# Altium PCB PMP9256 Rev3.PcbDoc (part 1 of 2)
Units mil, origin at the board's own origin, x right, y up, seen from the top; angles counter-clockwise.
Board outline 5025 x 2070 mil, 4 copper layers (Top Layer, MidLayer1, MidLayer2, Bottom Layer), stack 90 mil thick; 116 components, 45 nets, 245 pads, 340 vias.
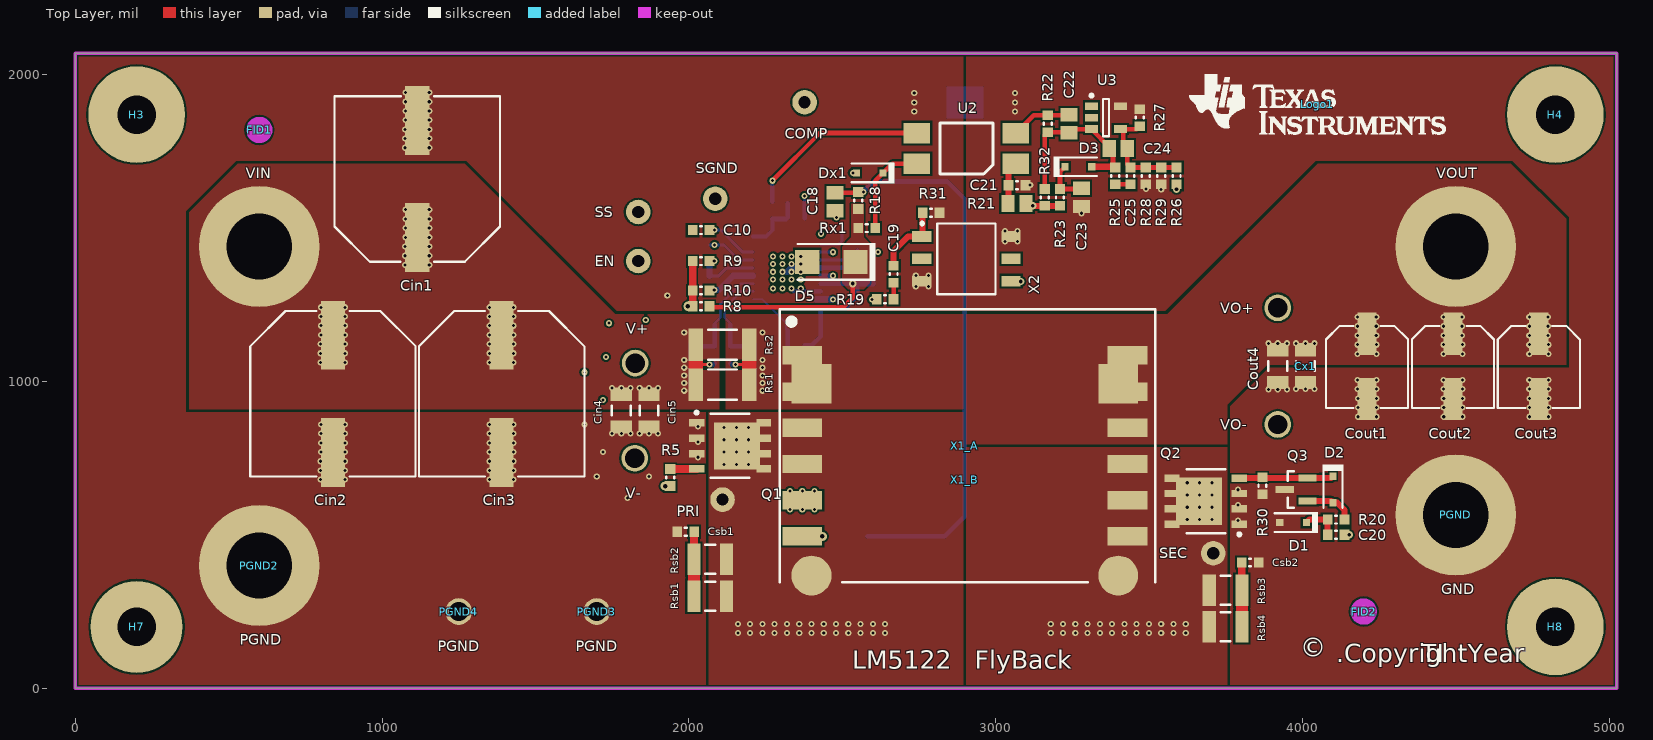
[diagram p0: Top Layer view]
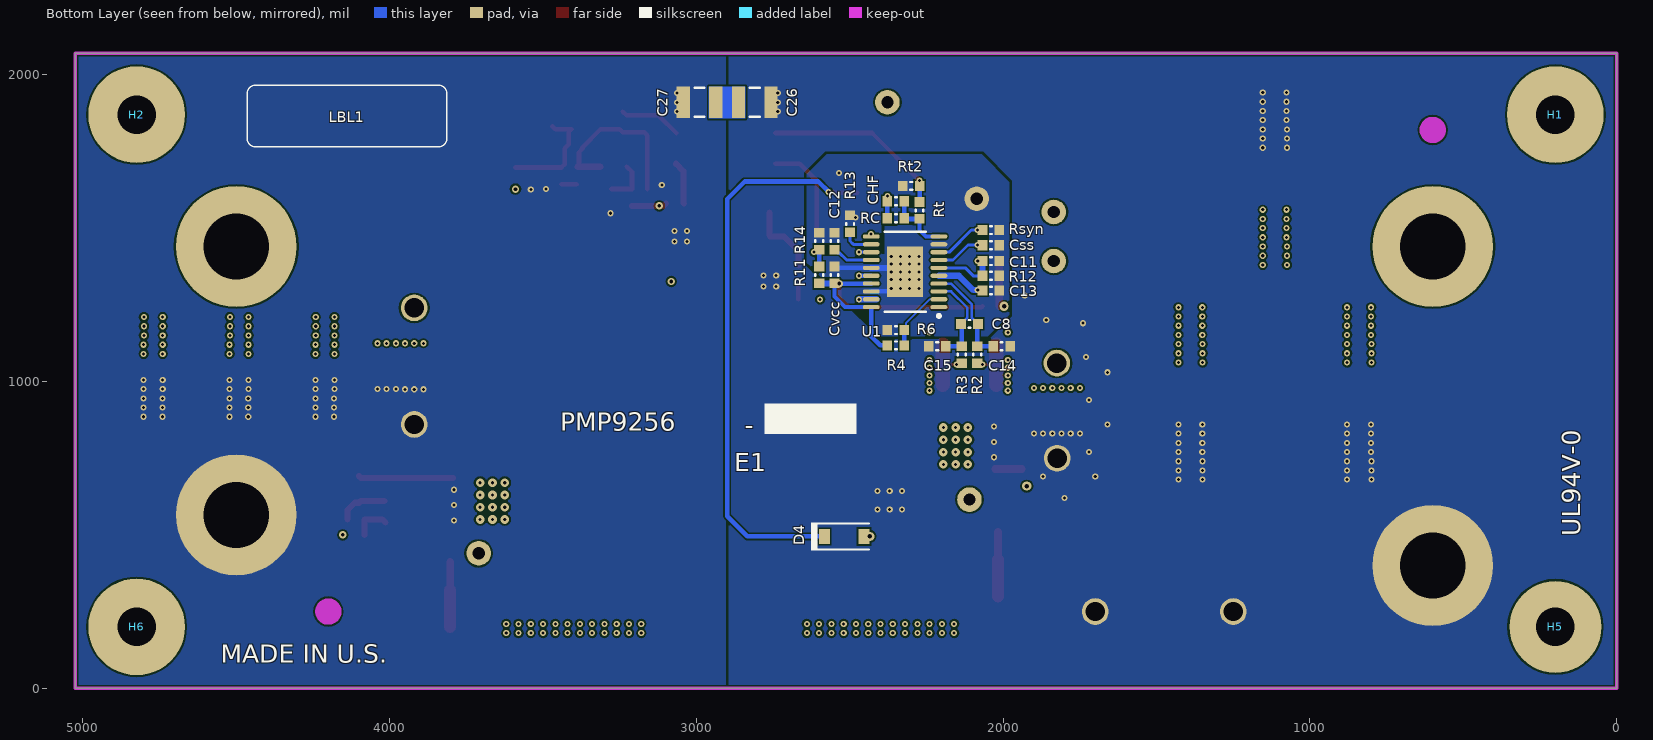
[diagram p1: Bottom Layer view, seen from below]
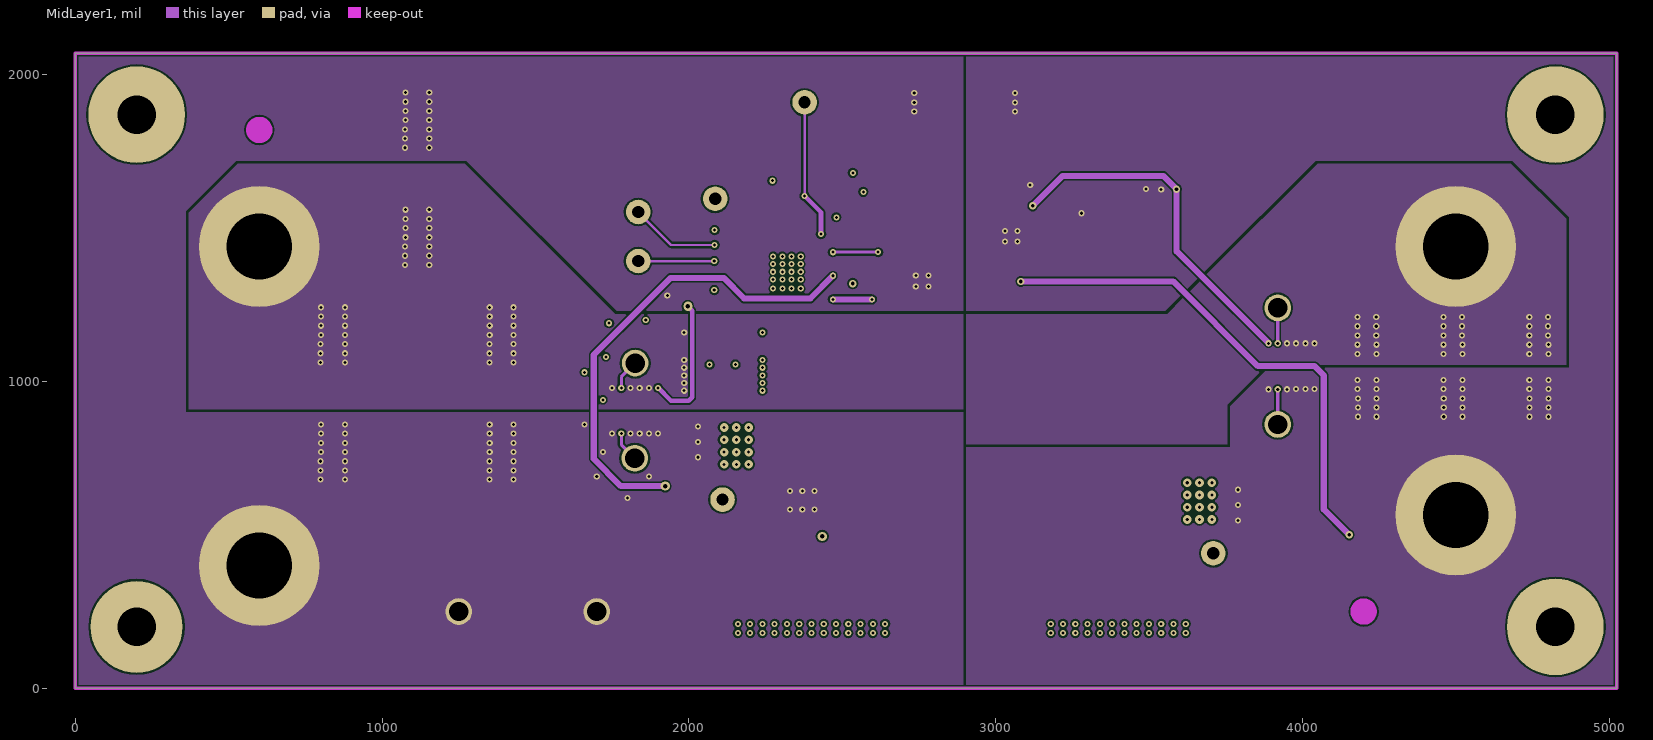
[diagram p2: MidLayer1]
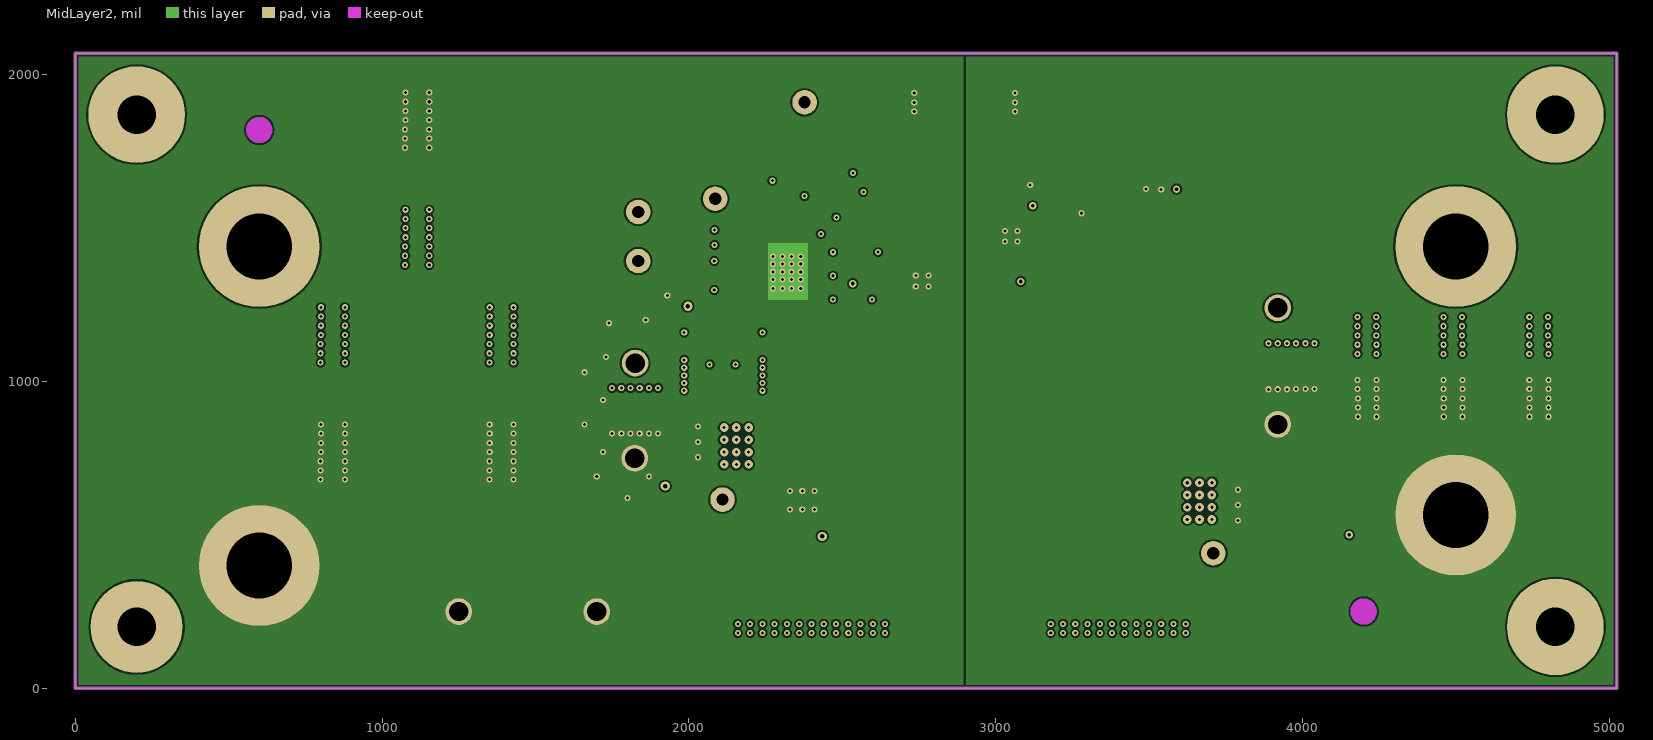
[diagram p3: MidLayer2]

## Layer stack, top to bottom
Top Solder: solder mask 0.4, Solder Resist, Dk 3.5
Top Layer: signal copper 1.4
Dielectric1: core 59.2, FR-4, Dk 4.8
MidLayer1: signal copper 1.4
Dielectric2: prepreg 12.6, FR-4, Dk 4.8
MidLayer2: signal copper 1.4
Dielectric3: core 12.6, FR-4, Dk 4.8
Bottom Layer: signal copper 1.4
Bottom Solder: solder mask 0.4, Solder Resist, Dk 3.5

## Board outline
0,0 0,2070 5025,2070 5025,0

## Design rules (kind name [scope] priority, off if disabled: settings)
AcuteAngle [All] p1: minimum=4.50000000000000E+0001 checktracksonly=FALSE
AssemblyTestPointUsage [All] p1: valid=2
Clearance [All] p1: gap=6
ComponentClearance ComponentClearance_1 [HasFootprint('PA2398NL') vs HasFootprint('PA6605-AL')] p1: gap=0 collisioncheckmode=3 verticalgap=0 showdistances=FALSE
ComponentClearance Standoffs [(HasFootprint('NY PMS 440 0025 PH')) vs HasFootprint('Keystone_1902C')] p2: gap=0 collisioncheckmode=3 verticalgap=0 showdistances=FALSE
ComponentClearance [All] p3: gap=10 collisioncheckmode=3 verticalgap=10 showdistances=FALSE
DiffPairsRouting [All] p1: maxlimit=100 minlimit=10 mostfreqgap=10 toplayer_minwidth=15 toplayer_maxwidth=15 toplayer_prefwidth=15 midlayer1_minwidth=15 midlayer1_maxwidth=15 midlayer1_prefwidth=15 midlayer2_minwidth=15 midlayer2_maxwidth=15 midlayer2_prefwidth=15 bottomlayer_minwidth=15 bottomlayer_maxwidth=15 bottomlayer_prefwidth=15 maxuncoupledlength=1000
FabricationTestPointUsage TestPointUsage [All] p1: valid=2 allowmultiple=FALSE
FabricationTestpoint Testpoint [All] p1: side=3 testpointundercomponent=TRUE minsize=40 maxsize=100 preferedsize=60 minholesize=0 maxholesize=40 preferedholesize=32 testpointgrid=1 allowsidetop=TRUE allowsidebottom=TRUE usegrid=TRUE gridtolerance=0.01
FanoutControl Fanout_LCC [IsLCC] p1: bgadir=Out bgaviamode=Centered fanoutstyle=Auto fanoutdirection=Alternating viagrid=1 // Fanout_LCC (Default Rule)
FanoutControl Fanout_BGA [IsBGA] p2: bgadir=Out bgaviamode=Centered fanoutstyle=Auto fanoutdirection=Alternating viagrid=1 // Fanout_BGA (Default Rule)
FanoutControl Fanout_SOIC [IsSOIC] p3 off: bgadir=Out bgaviamode=Centered fanoutstyle=Auto fanoutdirection=Alternating viagrid=1 // Fanout_SOIC (Default Rule)
FanoutControl Fanout_Default [All] p4: bgadir=Out bgaviamode=Centered fanoutstyle=Auto fanoutdirection=Alternating viagrid=1 // Fanout_Default (Default Rule)
FanoutControl Fanout_Small [(CompPinCount < 5)] p5 off: bgadir=Out bgaviamode=Centered fanoutstyle=Auto fanoutdirection=OutThenIn viagrid=1 // Fanout_Small (Default Rule)
HoleSize [All] p1: absolutevalues=TRUE maxlimit=500 minlimit=8 maxpercent=80.000 minpercent=20.000
MinimumAnnularRing [All] p1: minimumring=5
MinimumSolderMaskSliver MinimumSolderMaskSliver_Logo [InComponentClass('Logo') vs InComponentClass('Logo')] p1: minsoldermaskwidth=0
MinimumSolderMaskSliver [All] p2: minsoldermaskwidth=0
PlaneClearance [All] p1: clearance=10
PlaneConnect [All] p1: planeconnectstyle=Direct reliefexpansion=10 reliefentries=4 reliefconductorwidth=10 reliefairgap=10
PolygonConnect [All] p1: connectstyle=Direct reliefconductorwidth=10 reliefentries=4 polygonreliefangle="90 Angle" airgapwidth=10
RoutingVias [All] p1: holewidth=16 width=34 viastyle="Through Hole" minholewidth=8 minwidth=10 maxholewidth=40 maxwidth=65
SMDToCorner [All] p1: distance=0
SilkToSilkClearance [All] p1: silktosilkclearance=0
SilkToSolderMaskClearance SilkscreenOverComponentPads [IsPad] p1: minsilkscreentomaskgap=1 clearancetoexposedcopper=TRUE
SolderMaskExpansion [All] p1: expansion=3
UnpouredPolygon [All] p1: allowunpoured=FALSE
Width [All] p1: maxlimit=100 minlimit=6 preferedwidth=10 checkconnectedcopper=TRUE
13 further rules are at their usual default settings.

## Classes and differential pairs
component class "PMP9256 Rev8 Schematic": C8 C10 C11 C12 C13 C14 C15 C18 C19 C20 C21 C22 C23 C24 C25 C26 C27 CHF Cin1 Cin2 Cin3 Cin4 Cin5 COMP Cout1 Cout2 Cout3 Cout4 Csb1 Csb2 Css Cvcc Cx1 D1 D2 D3 D4 D5 Dx1 EN PGND PGND2 PGND3 PGND4 PRI Q1 Q2 Q3 R2 R3 R4 R5 R6 R8 R9 R10 R11 R12 R13 R14 R18 R19 R20 R21 R22 R23 R25 R26 R27 R28 R29 R30 R31 R32 RC Rs1 Rs2 Rsb1 Rsb2 Rsb3 Rsb4 Rsyn Rt Rt2 Rx1 SEC SGND SS U1 U2 U3 V+ V- VIN VO+ VO- VOUT X1_A X1_B X2
component class "Mounting Holes": H3 H4 H7 H8
component class Logo: Logo1
component class Hardware_ANSI-B: FID1 FID2 H1 H2 H3 H4 H5 H6 H7 H8 LBL1 Logo1 ZZ1 ZZ2 ZZ3 ZZ4
component class FiducialMark: FID1 FID2
component class AssemblyNote: ZZ1 ZZ2 ZZ3 ZZ4
component class Label: LBL1

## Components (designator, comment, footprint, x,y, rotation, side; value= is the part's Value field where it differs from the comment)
C8 "GRM1885C1H561JA01D" 0603L 2110,1187.56 r180 bottom
C10 "GRM1885C1H101JA01D" 0603L 2040,1493.56 r180 top
C11 "GRM1885C1H101JA01D" 0603L 2040,1392.56 r180 bottom
C12 "GRM188R71E473KA01D" 0603L 2550,1457.56 r90 bottom
C13 "GRM188R71E474KA12D" 0603L 2040,1296.56 r180 bottom
C14 "GRM1885C1H470JA01D" 0603L 2005,1115.12 r0 bottom
C15 "GRM1885C1H470JA01D" 0603L 2215,1115.12 r0 bottom
C18 "DNP" 0805L 2476,1586 r270 top
C19 "GRM188R71E473KA01D" 0603L 2667.56,1350 r90 top
C20 "GRM188R71E473KA01D" 0603L 4110,500 r180 top
C21 "C1608X7R1C105K" 0603L 3070,1640 r0 top
C22 "DNP" 0805L 3240,1840 r90 top
C23 "GRM21BR61C106KE15L" 0805L 3280,1600 r270 top
C24 "08051A101FAT2A" 0805L 3400,1760 r0 top
C25 "GRM188R71H104KA93D" 0603L 3440,1670 r270 top
C26 "Vishay, VJ1210Y222KBRAT4X" 1210L 2810,1910 r180 bottom
C27 "VJ1210Y222KXGAT5Z" 1210L 2990,1910 r180 bottom
CHF "GRM1885C1H101JA01D" 0603L 2350,1587.56 r180 bottom (schematic designator Chf)
Cin1 "EEV-FK1J221Q" SM_RADIAL_H13 1115,1660 r90 top
Cin2 "EEV-FK1J221Q" SM_RADIAL_H13 840,960 r270 top
Cin3 "EEV-FK1J221Q" SM_RADIAL_H13 1390,960 r270 top
Cin4 "C3216X7R2A105M" 1206L 1780,905 r270 top
Cin5 "C3216X7R2A105M" 1206L 1870,905 r270 top
COMP "5002" Keystone5002 2377.56,1910 r90 top
Cout1 "20SVPF120M" CAPSMT_62_F61 4210,1050 r270 top
Cout2 "20SVPF120M" CAPSMT_62_F61 4490,1050 r270 top
Cout3 "20SVPF120M" CAPSMT_62_F61 4770,1050 r270 top
Cout4 "GRM31CR61C226KE15L" 1206L 3920,1050 r270 top
Csb1 "GRM1885C1H821JA01D" 0603L 1990,510 r180 top
Csb2 "GRM1885C1H821JA01D" 0603L 3830,410 r0 top
Css "GRM188R71H103KA01D" 0603L 2040,1444.56 r180 bottom
Cvcc "C0603C475K8PACTU" 0603L 2550,1347.56 r270 bottom
Cx1 "GRM31CR61C226KE15L" 1206L 4010,1050 r270 top
D1 "BAT54HT1G" sod-323 3970,540 r180 top
D2 "BAS 16-03W E6327" sod-323 4100,648 r270 top
D3 "BAS 16-03W E6327" sod-323 3270,1700 r0 top
D4 "BAV21W-7-F" SOD-123 2518,495 r180 bottom
D5 "BZG03C15G" SMA 2465,1390 r180 top
Dx1 "MMSZ5231BS-7-F" sod-323 2590,1680 r180 top
EN "5002" KEYSTONE5002 1835,1392.56 r90 top
FID1 "Fiducial" Fiducial10-20 600,1820 r90 top
FID2 "Fiducial" Fiducial10-20 4200,250 r0 top
H1 "1902C" Keystone_1902C 200,1870 r180 bottom locked
H2 "1902C" Keystone_1902C 4825,1870 r180 bottom locked
H3 "NY PMS 440 0025 PH" "NY PMS 440 0025 PH"#1 200,1870 r0 top locked
H4 "NY PMS 440 0025 PH" "NY PMS 440 0025 PH"#1 4825,1870 r0 top locked
H5 "1902C" Keystone_1902C 200,200 r180 bottom locked
H6 "1902C" Keystone_1902C 4825,200 r180 bottom locked
H7 "NY PMS 440 0025 PH" "NY PMS 440 0025 PH"#2 200,200 r0 top locked
H8 "NY PMS 440 0025 PH" "NY PMS 440 0025 PH"#1 4825,200 r0 top locked
LBL1 "Size: 0.65\" x 0.20 \"" Label_650x200 4139,1865.31 r180 bottom
Logo1 "Texas Instruments" TI_Stacked_Overlay_Small 4049.42,1903 r0 top
PGND "GND" Keystone_575-4 4500,565 r270 top
PGND2 "PGND" Keystone_575-4 600,400 r270 top
PGND3 "PGND" Keystone5011 1700,250 r90 top
PGND4 "PGND" Keystone5011 1250,250 r90 top
PRI "5002" KEYSTONE5002 2110,615 r270 top
Q1 "SI7898DP-E3" PowerPAK_SO-8 2135,790 r0 top
Q2 "SI7898DP-E3" PowerPAK_SO-8 3685,610 r180 top
Q3 "MMBT3906" SOT-23 3980,648 r180 top
R2 "CRCW0603182RFKEA" 0603L 2085,1087.56 r270 bottom
R3 "CRCW0603182RFKEA" 0603L 2135,1087.56 r270 bottom
R4 "CRCW0603158KFKEA" 0603L 2350,1117.56 r0 bottom
R5 "ERJ-3GEY0R00V" 0603L 1940,687 r270 top
R6 "ERJ-3GEY0R00V" 0603L 2350,1167.56 r180 bottom
R8 "ERJ-3GEY0R00V" 0603L 2040,1245 r0 top
R9 "CRCW060340K2FKEA" 0603L 2040,1392.56 r180 top
R10 "CRCW06033R30JNEA" 0603L 2040,1296.56 r180 top
R11 "ERJ-3GEY0R00V" 0603L 2600,1347.56 r270 bottom
R12 "CRCW06038K66FKEA" 0603L 2040,1344.56 r0 bottom
R13 "CRCW0603100KFKEA" 0603L 2499.27,1513.86 r270 bottom
R14 "ERJ-3GEY0R00V" 0603L 2600,1457.56 r270 bottom
R18 "DNP" 0603L 2552.44,1590 r90 top
R19 "CRCW06032R20JNEA" 0603L 2640,1267.73 r180 top
R20 "CRCW06032R20JNEA" 0603L 4110,550 r0 top
R21 "CRCW080510R0FKEA" 0805L 3070,1580 r0 top
R22 "CRCW060310K0FKEA" 0603L 3170,1840 r90 top
R23 "CRCW060347K5FKEA" 0603L 3210,1600 r270 top
R25 "CRCW060340K2FKEA" 0603L 3390,1670 r270 top
R26 "CRCW060341K2FKEA" 0603L 3590,1670 r270 top
R27 "CRCW06034K99FKEA" 0603L 3470,1860.11 r270 top
R28 "DNP" 0603L 3490,1670 r90 top
R29 "DNP" 0603L 3540,1670 r90 top
R30 "CRCW06031K00FKEA" 0603L 3870,660 r90 top
R31 "CRCW06034K99FKEA" 0603L 2790,1550 r180 top
R32 "DNP" 0603L 3160,1600 r90 top
RC "CRCW060320K0FKEA" 0603L 2350,1532.56 r0 bottom (schematic designator Rc)
Rs1 "WSL2010R0100FEA18" 2010L 2110,990 r0 top
Rs2 "WSL2010R0100FEA18" 2010L 2110,1120 r0 top
Rsb1 "ERJ-14NF34R0U" 1210L 2070,300 r0 top
Rsb2 "ERJ-14NF34R0U" 1210L 2070,420 r0 top
Rsb3 "ERJ-14NF34R0U" 1210L 3750,320 r180 top
Rsb4 "ERJ-14NF34R0U" 1210L 3750,200 r180 top
Rsyn "CRCW060340K2FKEA" 0603L 2040,1493.56 r0 bottom
Rt "CRCW060310K0FKEA" 0603L 2273,1557.56 r270 bottom
Rt2 "CRCW06031K00FKEA" 0603L 2300,1637.56 r180 bottom
Rx1 "CRCW06031K00FKEA" 0603L 2580,1500 r180 top
SEC "5002" KEYSTONE5002 3710,440 r270 top
SGND "SGND" KEYSTONE5001 2086,1595.56 r90 top
SS "5002" Keystone5002 1835,1552.56 r90 top
U1 "LM5122" MXA20A_L 2320,1357.56 r0 bottom
U2 "PS2501L-1-A" PS2501L 2905,1760 r180 top
U3 "TI, LMV431ACM5" MF05A_N 3360,1860 r0 top
V+ "5010" Keystone5010 1825,1060 r270 top
V- "5011" Keystone5011 1824,750 r90 top
VIN "575-4" Keystone_575-4 600,1440 r270 top
VO+ "5010" Keystone5010 3920,1240 r0 top
VO- "5011" Keystone5011 3920,860 r0 top
VOUT "575-4" Keystone_575-4 4500,1440 r270 top
X1_A "PA2398NL" PA2398NL 2900,790 r270 top
X1_B "PA6605-AL" PA6605-AL 2900,680 r0 top
X2 "DA2319-ALB" DA2319-ALB 2905,1400 r0 top
ZZ1 "This Assembly Note is for PCB labels only" AssemblyNoteLabel -743,4380 r0 top
ZZ2 "These assemblies are ESD sensitive, ESD precautions shall be observed." AssemblyNote -752,4163 r0 top
ZZ3 "These assemblies must be clean and free from flux and all contaminants. Use of no clean flux is not acceptable." AssemblyNote -728,3944 r0 top
ZZ4 "These assemblies must comply with workmanship standards IPC-A-610 Class 2., unless otherwise specified." AssemblyNote -714,3705 r0 top

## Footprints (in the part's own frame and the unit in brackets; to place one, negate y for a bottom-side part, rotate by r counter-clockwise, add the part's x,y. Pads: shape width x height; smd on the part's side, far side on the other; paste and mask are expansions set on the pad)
0603L [mm] "0603 from SM-752 data"
  rect 0.8x0.85 smd: 1(-0.7,0) 2(0.7,0)
  silkscreen extent -0.07,-0.33 0.07,0.33, body extent -0.87,-0.47 0.87,0.47, height 0.85
0805L [mm] "0805 from SM-752 data"
  rect 1.1x1.4 smd: 1(-0.75,0) 2(0.75,0)
  body extent -1.1,-0.72 1.1,0.72, height 1.1
1206L [mm] "1206 from SM-752 data"
  rect 1.1x1.75 smd: 1(-1.35,0) 2(1.35,0)
  silkscreen extent -0.4,-0.77 0.4,0.77, body extent -1.7,-0.9 1.7,0.9, height 1.35
1210L [mm] "1210 from SM-752 data"
  rect 1.1x2.6 smd: 1(-1.35,0) 2(1.35,0)
  silkscreen extent -0.4,-1.2 0.4,1.2, body extent -1.7,-1.35 1.7,1.35, height 1.35
2010L [mm]
  rect 1.2x2.7 smd: 1(-2.2,0) 2(2.2,0)
  silkscreen extent -1.2,-1.25 1.2,1.25, body extent -2.73,-1.45 2.73,1.45, height 1.66
AssemblyNote [mil] "Assembly Note"
AssemblyNoteLabel [mil] "Assembly Note for PCB Labels"
CAPSMT_62_F61 [mm] "6.3 x 5.8mm:  Chemi-Con F61"
  rect 3.5x1.6 smd: 1(-2.675,0.025) 2(2.725,0.025)
  silkscreen extent -3.34,-3.38 3.46,3.42, body extent -3.39,-3.39 3.46,3.43, height 6.1
DA2319-ALB [mil] "Gate Transformer"
  rect 63x35 smd: 1(-145.5,73) 2(-145.5,0) 3(-145.5,-73) 4(145.5,-73) 5(145.5,0) 6(145.5,73)
  silkscreen extent -148,-115 95,119, body extent -162,-110 162,110, height 213
Fiducial10-20 [mm]
  round 1 smd paste-0.5 mask+0.5: 1(0,0)
  Keep-Out Layer circle w1.178: c0,0 r0.5
KEYSTONE5001 [mil] "For Keystone 500x miniature loop terminals"
  round 80 hole 40: 1(0,0)
  body extent -49,-49 49,49, height 182
Keystone5002 [mil] "For Keystone 500x miniature loop terminals"
  round 80 hole 40: 1(0,0)
  body extent -49,-49 49,49, height 182
KEYSTONE5002 [mil] "For Keystone 500x miniature loop terminals"
  round 80 hole 40: 1(0,0)
  body extent -49,-49 49,49, height 182
Keystone5010 [mil] "Keystone Multipurpose loops"
  round 87 hole 63: 1(0,0)
  body extent -63,-63 63,62, height 319
Keystone5011 [mil] "Keystone Multipurpose loops"
  round 87 hole 63: 1(0,0)
  body extent -63,-63 63,62, height 319
Keystone_575-4 [mm] "Banana Jack"
  round 10 hole 5.45: 1(0,0)
  body extent -3.95,-3.95 3.92,3.93, height 2.36
Keystone_1902C [mil] "Hex Standoff, 4-40 threaded, nylon"
  body extent -145,-126 146,126, height 501
Label_650x200 [mil] "Thermal Transfer Label"
  silkscreen extent -325,-100 325,100, body extent -326,-101 326,101, height 1
MF05A_N [mm] "SOT23, 5-Leads, Body 2.9x1.6mm, Pitch 0.95mm, Lead Span 2.8mm, IPC Medium Density"
  rect 1.1x0.65 smd: 1(-1.2,0.95) 2(-1.2,0) 3(-1.2,-0.95) 4(1.2,-0.95) 5(1.2,0.95)
  silkscreen extent -1.32,-1.55 0.25,1.95, body extent -0.9,-1.55 0.9,1.55, height 1.19
MXA20A_L [mm] "TSOP, 20-Leads, Body 6.5x4.4mm, Pitch 0.65mm, Exposed Pad, IPC High Density"
  oval 1.4x0.35 smd: 1(-2.8,2.925) 2(-2.8,2.275) 3(-2.8,1.625) 4(-2.8,0.975) 5(-2.8,0.325) 6(-2.8,-0.325) 7(-2.8,-0.975) 8(-2.8,-1.625) 9(-2.8,-2.275) 10(-2.8,-2.925) 11(2.8,-2.925) 12(2.8,-2.275) 13(2.8,-1.625) 14(2.8,-0.975) 15(2.8,-0.325) 16(2.8,0.325) 17(2.8,0.975) 18(2.8,1.625) 19(2.8,2.275) 20(2.8,2.925)
  rect 3x4.2 smd: 21(0,0)
  silkscreen extent -2.92,-3.3 1.7,3.77, body extent -2.25,-3.3 2.25,3.3, height 1.1
"NY PMS 440 0025 PH"#1 [mm] "4-40 nylon screw and mounting hole"
  round 8 hole 3.2: ""(0,0)
  body extent -3.3,-3.3 3.3,3.3, height 2.69
"NY PMS 440 0025 PH"#2 [mm] "4-40 nylon screw and mounting hole"
  round 7.62 hole 3.2: ""(0,0)
  body extent -3.3,-3.3 3.3,3.3, height 2.69
PA2398NL [mil] "Transformer"
  rect 60x130 smd: 1(-295,-530) 2(-177,-530) 3(-59,-530) 4(59,-530) 5(177,-530) 6(295,-530) 7(295,530) 8(177,530) 9(59,530) 10(-59,530) 11(-177,530) 12(-295,530)
  silkscreen extent -445,-603 445,620, body extent -430,-575 430,575, height 450
PA6605-AL [mil] "Transformer"
  rect 130x130 smd: 1(-500,312.5) 4(500,312.5)
  round 130 smd: 2(-500,-312.5) 3(500,-312.5)
  body extent -590,-525 590,525, height 536
PowerPAK_SO-8 [mil] "Vishay PowerPAK SO-8, Body 5.3x6.0mm (max), Pitch 1.27mm, IPC Medium Density"
  rect 50x24 smd mask+2.99: 1(-109.5,75) 2(-109.5,25) 3(-109.5,-25) 4(-109.5,-75)
  rect 48x24 smd mask+2.99: 5(109.5,-75) 8(109.5,75)
  rect 48x24 smd paste-12 mask+2.99: 6(109.5,-25) 7(109.5,25)
  rect 150x154 smd paste-75 mask+2.99: 9(22.5,0)
  silkscreen extent -114,-104 62,113, body extent -121,-102 121,102, height 43
PS2501L [mm] "NEC optocoupler"
  rect 2.2x1.7 smd: 1(-4.1,1.27) 2(-4.1,-1.27) 3(4.1,-1.27) 4(4.1,1.27)
  silkscreen extent -2.2,-2.1 2.2,2.12, body extent -5,-2.29 5,2.29, height 3.87
SM_RADIAL_H13 [mm] "12.5 x 13.5mm:  Panasonic H13"
  rect 5.7x2 smd: 1(-4.85,0) 2(4.85,0)
  silkscreen extent -6.85,-6.85 6.85,6.85, body extent -6.85,-6.85 6.85,6.85, height 14
SMA [mm] "Molded Diode, 2-Leads, Body 4.3x2.6mm, IPC Medium Density, based on OnSemi component dimensions and land pattern"
  rect 2x2 smd: 1(-2,0) 2(2,0)
  silkscreen extent -3.66,-1.57 2.79,1.57, body extent -2.6,-1.3 2.6,1.3, height 2.42
SOD-123 [mm] "On Semi recommended land pattern"
  rect 0.915x1.22 smd: 1(-1.637,0) 2(1.637,0)
  silkscreen extent -2.74,-1.17 2.03,1.17, body extent -1.93,-0.9 1.93,0.9, height 1.35
sod-323 [mm] "NXP recommended land pattern"
  rect 0.6x0.6 smd paste-0.05: 1(-1.1,0) 2(1.1,0)
  silkscreen extent -2.06,-0.86 1.53,0.86, body extent -1.3,-0.67 1.3,0.68, height 1.1
SOT-23 [mm] "SOT23, 3-Leads, Body 2.9x1.3mm, Pitch 0.95mm, Lead Span 2.5mm, IPC Medium Density"
  rect 1.5x0.6 smd: 1(-0.95,0.95) 2(-0.95,-0.95) 3(0.95,0)
  silkscreen extent 0.2,-1.5 0.7,1.5, body extent -1.16,-1.45 1.21,1.45, height 1
TI_Stacked_Overlay_Small [mil]
  silkscreen extent -418,-98 418,98

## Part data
C8: "CAP, CERM, 560pF, 50V, +/-5%, C0G/NP0, 0603"
C10 C11 CHF: "CAP, CERM, 100pF, 50V, +/-5%, C0G/NP0, 0603"
C12 C19 C20: "CAP, CERM, 0.047uF, 25V, +/-10%, X7R, 0603"
C13: "CAP, CERM, 0.47uF, 25V, +/-10%, X7R, 0603"
C14 C15: "CAP, CERM, 47pF, 50V, +/-5%, C0G/NP0, 0603"
C18: library part GRM21BR61C106KE15L, "CAP, CERM, 10uF, 16V, +/-10%, X5R, 0805"
C21: "CAP, CERM, 1uF, 16V, +/-10%, X7R, 0603"
C22: library part C2012Y5V1H105Z, "Capacitor"
C23: "CAP, CERM, 10uF, 16V, +/-10%, X5R, 0805"
C24: "CAP, CERM, 100pF, 100V, +/-1%, C0G/NP0, 0805"
C25: "CAP, CERM, 0.1uF, 50V, +/-10%, X7R, 0603"
C26: library part VJ1210Y222KXGAT5Z, "CAP, CERM, 2200pF, 1000V, +/-10%, X7R, 1210"
C27: "CAP, CERM, 2200pF, 1000V, +/-10%, X7R, 1210"
Cin1 Cin2 Cin3: "CAP, AL, 220uF, 63V, +/-20%, 0.16 ohm, SMD"
Cin4 Cin5: "CAP, CERM, 1uF, 100V, +/-20%, C Series, 1206"
COMP EN SS: "Test Point, TH, Miniature, White"
Cout1 Cout2 Cout3: "CAP, AL, 120uF, 20V, +/-20%, 0.025 ohm, SMD"
Cout4 Cx1: "CAP, CERM, 22uF, 16V, +/-10%, X5R, 1206"
Csb1 Csb2: "CAP, CERM, 820pF, 50V, +/-5%, C0G/NP0, 0603"
Css: "CAP, CERM, 0.01uF, 50V, +/-10%, X7R, 0603"
Cvcc: "CAP, CERM, 4.7uF, 10V, +/-10%, X5R, 0603"
D1: "Diode, Schottky, 30V, 0.2A, SOD-323"
D2 D3: library part Diode, "DIODE SWITCH 80V 0.25A SOD323-2"
D4: "Diode, Switching, 200V, 0.2A, SOD-123"
D5: "Diode, Zener, 15V, 1.5W, SMA"
Dx1: "Diode, Zener, 5.1V, 200mW, SOD-323"
FID1 FID2: "Fiducial mark.  There is nothing to buy or mount."
H1 H2 H5 H6: "Standoff, Hex, 0.5\"L #4-40 Nylon"
H3 H4 H7 H8: "Machine Screw, Round, #4-40 x 1/4, Nylon, Philips panhead"
LBL1: library part THT-14-423-10, "Thermal Transfer Printable Labels, 0.650\" W x 0.200\" H - 10,000 per roll"
Logo1: library part TI_Logo, "Texas Instrument Corporate Signature"
PGND PGND2: library part 575-4, "Standard Banana Jack, Uninsulated, 5.5mm"
PGND3 PGND4: library part 5011, "Test Point, TH, Multipurpose, Black"
PRI SEC: "Test Point, Miniature, White, TH"
Q1 Q2: "MOSFET, N-CH, 150V, 3A, PowerPAK SO-8"
Q3: library part "MMBT3906, Fairchild Semiconductor", "Transistor, PNP, 40V, 0.2A, SOT-23"
R2 R3: "RES, 182 ohm, 1%, 0.1W, 0603"
R4: "RES, 158k ohm, 1%, 0.1W, 0603"
R5 R6 R8 R11 R14: "RES, 0 ohm, 5%, 0.1W, 0603"
R9 R25 Rsyn: "RES, 40.2k ohm, 1%, 0.1W, 0603"
R10: "RES, 3.3 ohm, 5%, 0.1W, 0603"
R12: "RES, 8.66k ohm, 1%, 0.1W, 0603"
R13: "RES, 100k ohm, 1%, 0.1W, 0603"
R18: library part CRCW06030000Z0EA, "RES, 0 ohm, 5%, 0.1W, 0603"
R19 R20: "RES, 2.2 ohm, 5%, 0.1W, 0603"
R21: "RES, 10.0 ohm, 1%, 0.125W, 0805"
R22 Rt: "RES, 10.0k ohm, 1%, 0.1W, 0603"
R23: "RES, 47.5k ohm, 1%, 0.1W, 0603"
R26: "RES, 41.2k ohm, 1%, 0.1W, 0603"
R27 R31: "RES, 4.99k ohm, 1%, 0.1W, 0603"
R28: library part CRCW06032K26FKEA, "RES, 2.26k ohm, 1%, 0.1W, 0603"
R29: library part CRCW0603442RFKEA, "RES, 442 ohm, 1%, 0.1W, 0603"
R30 Rt2 Rx1: "RES, 1.00k ohm, 1%, 0.1W, 0603"
R32: library part CRCW060310K0FKEA, "RES, 10.0k ohm, 1%, 0.1W, 0603"
RC: "RES, 20.0k ohm, 1%, 0.1W, 0603"
Rs1 Rs2: "RES, 0.01 ohm, 1%, 1W, 2010"
Rsb1 Rsb2 Rsb3 Rsb4: library part MCR25JZHJ000, "RES 34 OHM 1/2W 1% 1210 SMD"
SGND: library part 5001, "Test Point, TH, Miniature, Black"
U2: "High Isolation Voltage Single Transistor Type OptoCoupler"
U3: library part LMV431ACM5, "Low-Voltage (1.24V) Adjustable Precision Shunt Regulator, 5-pin SOT-23"
V+ VO+: "Test Point, Multipurpose, Red, TH"
V- VO-: "Test Point, TH, Multipurpose, Black"
VIN VOUT: "Standard Banana Jack, Uninsulated, 5.5mm"
X1_A: library part PA2398
X1_B: library part PA6605
ZZ1: library part AssemblyNoteLabel
ZZ2 ZZ3 ZZ4: library part AssemblyNote

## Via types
v1: diameter 20, hole 10, Top Layer to Bottom Layer, tented both sides, 258 vias
v2: diameter 20, hole 10, Top Layer to Bottom Layer, 50 vias
v3: diameter 28, hole 10, Top Layer to Bottom Layer, tented top, 24 vias
v4: diameter 24, hole 12, Top Layer to Bottom Layer, tented both sides, 5 vias
v5: diameter 30, hole 15, Top Layer to Bottom Layer, tented both sides, 3 vias

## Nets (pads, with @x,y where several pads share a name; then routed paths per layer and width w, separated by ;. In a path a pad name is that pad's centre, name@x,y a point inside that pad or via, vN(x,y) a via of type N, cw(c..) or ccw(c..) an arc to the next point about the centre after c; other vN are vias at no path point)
COMP: CHF.1 COMP.1 RC.2 U1.11 | length 506.6
  MidLayer1 w8: v1(2377.56,1604.56) COMP.1@2377.56,1910
  MidLayer1 w15: v1(2377.56,1604.56) 2431,1551.12 v1(2431,1480.56)
  Bottom Layer w15: RC.2@2377.56,1532.56 CHF.1@2377.56,1587.56
CSN: C8.1 C15.1 R3.1 U1.3 | length 298.6
  Bottom Layer w8: C8.1@2137.56,1187.56 2117,1208.12 2117,1240.58 2170,1293.58 U1.3@2209.76,1293.58
  Bottom Layer w15: C8.1@2135,1185 R3.1@2135,1115.12 C15.1@2187.44,1115.12
CSP: C8.2 C14.2 R2.1 U1.4 | length 329.6
  Bottom Layer w8: C8.2@2082.44,1187.56 2102,1207.12 2102,1250.56 2170.61,1319.17 U1.4@2209.76,1319.17
  Bottom Layer w15: C14.2@2032.56,1115.12 R2.1@2085,1115.12 C8.2@2085,1185
EXT_SYNC: C10.2
FB: CHF.2 RC.1 Rt.2 U1.10 | length 200.6
  Bottom Layer w13: U1.10@2209.76,1472.72 2252.16,1472.72 2272.47,1493.03 Rt.2@2272.47,1530
  Bottom Layer w15: Rt.2@2272.7,1529.77 RC.1@2318.31,1529.77 ; RC.1@2322.31,1533.77 CHF.2@2322.31,1580.64
HO: R19.2 U1.19 | length 184
  MidLayer1 w20: v1(2470,1267.73) v1@2597,1267.73
  Bottom Layer w20: U1.19@2413,1267.99 v1@2470,1267.99
  other v1: 2597,1267.46
"ISO GND": C21.2 C23.2 C27.1 Cout1.2 Cout2.2 Cout3.2 Cout4.2 Csb2.2 Cx1.2 D1.2 PGND.1 Q2.1 Q2.2 Q2.3 Q3.3 R27.1 R28.1 R29.1 R30.1 U3.5 VO-.1 X2.6 | length 114.5
  MidLayer1 w10: VO-.1@3920,860 v1(3920,974.5)
  other v1: 3790,547 3790,597 3790,647 4181,885 4242,885 4461,885 4522,885 4741,885 4802,885 4181,915 4242,915 4461,915 4522,915 4741,915 4802,915 4181,945 4242,945 4461,945 4522,945 4741,945 4802,945 3890,974.5 3950,974.5 4180,975 4242,975 4460,975 4522,975 4740,975 4802,975 3980,975.5 4010,975.5 4040,975.5 4180,1005 4242,1005 4460,1005 4522,1005 4740,1005 4802,1005 3031,1456 3072,1456 3031,1491 3072,1491 3280,1548.5 3540,1626 3490,1627 3113,1640 3064,1879.74 3064,1910 3064,1940
LO: R5.2 U1.16 | length 1590.8
  MidLayer1 w20: v5(1923,659) 1779,659 1690,748 1690,1086.79 1940.77,1337.56 2114,1337.56 2181,1270.56 2395.8,1270.56 v1(2470,1344.76)
  Bottom Layer w15: U1.16@2430.24,1344.76 v1(2470,1344.76)
MODE: R11.1 R14.2 U1.13 | length 241.6
  MidLayer1 w10: v1@2470,1421.56 v1(2617,1421.56)
  Bottom Layer w10: U1.13@2430.24,1421.54 v1(2470,1421.54)
  Bottom Layer w15: R11.1@2600,1375.12 R14.2@2600,1430
NetC18_1: C18.1 D4.1 R18.2 | length 1824.8
  Top Layer w15: C18.1@2476,1615.53 2550.41,1615.53 R18.2@2552.44,1617.56
  Bottom Layer w15: v1(2569,1618) 2603,1652 2843,1652 2900,1595 2900,561 2834,495 D4.1@2582.47,495
NetC19_1: C19.1 R19.1 | length 54.7
  Top Layer w15: R19.1@2667.56,1267.73 C19.1@2667.56,1322.44
NetC19_2: C19.2 R31.2 X2.1 | length 237.8
  Top Layer w10: X2.1@2759.5,1473 X2.1@2762.44,1475.94
  Top Layer w20: C19.2@2667.56,1377.56 2667.56,1425.58 2714.98,1473 X2.1@2759.5,1473 ; X2.1@2762.44,1475.94 R31.2@2762.44,1550
NetC20_1: C20.1 X2.4 | length 1669.1
  MidLayer1 w20: v4(3082,1326) 3579,1326 3855,1050 4040,1050 4070,1020 4070,583 v4(4153,500)
NetC20_2: C20.2 D1.1 R20.1 | length 123.3
  Top Layer w20: D1.1@4013.31,540 4023.31,550 R20.1@4082.44,550 C20.2@4082.44,500
NetC21_1: C21.1 R21.1 U2.1 | length 140.7
  Top Layer w20: R21.1@3040.47,1580 3042.44,1581.97 C21.1@3042.44,1640 3042.44,1686.02 U2.1@3066.42,1710
NetC22_1: C22.1 C24.1 D3.2 R22.1 R25.1 R32.2 U3.3 | length 565.8
  Top Layer w10: R25.1@3387.56,1700 R25.1@3390,1697.56
  Top Layer w15: R32.2@3160,1627.56 3160,1802.44 R22.1@3170,1812.44 3240,1812.44 3250.16,1822.6 U3.3@3312.76,1822.6 C24.1@3372.91,1762.44 ; C24.1@3370.47,1760 3383,1747.47 3383,1704.56 R25.1@3387.56,1700
  Top Layer w20: D3.2@3313.31,1700 R25.1@3387.56,1700
NetC22_2: C22.2 R22.2 U2.2 | length 202.4
  Top Layer w15: U2.2@3066.42,1810 3123.98,1867.56 3228.03,1867.56 C22.2@3240,1879.53
NetC23_1: C23.1 D3.1 R23.1 | length 150.2
  Top Layer w10: C23.1@3278.03,1627.56 C23.1@3280,1629.53
  Top Layer w15: D3.1@3226.69,1700 3210,1683.31 R23.1@3210,1627.56 C23.1@3278.03,1627.56
NetC24_2: C24.2 C25.1 R26.1 R27.2 R28.2 R29.2 U3.4 | length 355.5
  Top Layer w15: R27.2@3470,1832.55 3460.05,1822.6 U3.4@3407.24,1822.6 3416,1813.84 3416,1773.53 C24.2@3429.53,1760 3429.53,1708.03 C25.1@3440,1697.56 R26.1@3590,1697.56
NetC25_2: C25.2 R25.2 | length 50
  Top Layer w15: R25.2@3390,1642.44 C25.2@3440,1642.44
NetC26_1: C26.1 C27.2
NetCsb1_1: Csb1.1 Rsb1.1 Rsb2.1 | length 210
  Top Layer w25: Rsb2.1@2016.85,420 Csb1.1@2016.85,510
  Top Layer w40: Rsb1.1@2016.85,300 Rsb2.1@2016.85,420
NetCsb2_1: Csb2.1 Rsb3.1 Rsb4.1 | length 212.3
  Top Layer w25: Rsb3.1@3803,320.15 Csb2.1@3803,412.44
  Top Layer w40: Rsb4.1@3803.15,200 Rsb3.1@3803.15,320
NetD2_1: D2.1 Q2.4 Q3.2 R30.2 | length 307.5
  Top Layer w20: Q2.4@3794.5,685 Q3.2@4017,685 ; Q3.2@4017.4,685.4 4094.09,685.4 D2.1@4100,691.31
NetD2_2: D2.2 Q3.1 R20.2 | length 163.4
  Top Layer w20: Q3.1@4017.4,610.6 4094.09,610.6 D2.2@4100,604.69 4113.77,604.69 4137.56,580.9 R20.2@4137.56,550
NetD4_2: D4.2 X1_A.6
  other v5: 2435,495
NetDx1_1: Dx1.1 Rx1.1 U2.4 | length 313.4
  Top Layer w15: Rx1.1@2607.56,1500 2607.56,1654.25 Dx1.1@2633.31,1680 2663.31,1710 U2.4@2743.58,1710
NetQ1_4: Q1.4 R5.1 | length 85.5
  Top Layer w25: R5.1@1940,715 Q1.4@2025.5,715
NetRt2_2: Rt2.2 Rt.1 U2.3 | length 587.4
  Top Layer w15: v1(2272.44,1654.56) 2427.88,1810 U2.3@2743.58,1810
  Bottom Layer w15: Rt.1@2272.44,1585.68 Rt2.2@2272.44,1637.56
OPT: R4.1 R6.2 U1.2 | length 217.8
  Bottom Layer w6: U1.2@2209.76,1267.99 2239.57,1267.99 2317,1190.56 2317,1167.56 R6.2@2322.44,1167.56
  Bottom Layer w15: R4.1@2322.44,1117.56 R6.2@2322.44,1167.56
PGND: C14.1 C15.2 C26.2 Cin1.2 Cin2.2 Cin3.2 Cin4.2 Cin5.2 Csb1.2 PGND2.1 PGND3.1 PGND4.1 Q1.1 Q1.2 Q1.3 R31.1 V-.1 X1_A.5 X2.3 | length 99.2
  MidLayer1 w10: v1(1780,831) 1780,794 V-.1@1824,750
  other v1: 2330,583 2370,583 2410,583 1799.82,620 2330,643 2370,643 2410,643 800,680 879,680 1350,680 1429,680 1700,690 1870.13,690 800,710 879,710 1350,710 1429,710 800,740 879,740 1350,740 1429,740 2030,753 801,770 879,770 1351,770 1429,770 1720,770 801,800 879,800 1351,800 1429,800 2030,803 801,830 879,830 1351,830 1429,830 1750,831 1810,831 1840,831 1870,831 1900,831 2030,853 801,860 879,860 1351,860 1429,860 1660,860 1720,940 1660,1030 1730,1080 1740,1190 1859.61,1200 1930,1280 2740,1310 2781,1310 2740,1345 2781,1345 1075,1761.89 1154,1761.89 1075,1791.89 1154,1791.89 1075,1821.89 1154,1821.89 1076,1851.89 1154,1851.89 2735,1880.1 1076,1881.89 1154,1881.89 2735,1910 1076,1911.89 1154,1911.89 2735,1940.08 1076,1941.89 1154,1941.89
Q1-D: PRI.1 Q1.5 Q1.6 Q1.7 Q1.8 Q1.9 Rsb1.2 Rsb2.2 X1_A.3 X1_A.4 X1_B.2
  other v2: 2160,180 2200,180 2240,180 2280,180 2320,180 2360,180 2400,180 2440,180 2480,180 2520,180 2560,180 2600,180 2640,180 2160,210 2200,210 2240,210 2280,210 2320,210 2360,210 2400,210 2440,210 2480,210 2520,210 2560,210 2600,210 2640,210
  other v3: 2115,730 2155,730 2195,730 2115,770 2155,770 2195,770 2115,810 2155,810 2195,810 2115,850 2155,850 2195,850
Q2-D: Q2.5 Q2.6 Q2.7 Q2.8 Q2.9 Rsb3.2 Rsb4.2 SEC.1 X1_A.7 X1_A.8 X1_A.9 X1_B.3
  other v2: 3180,180 3220,180 3260,180 3300,180 3340,180 3380,180 3420,180 3460,180 3500,180 3540,180 3580,180 3620,180 3180,210 3220,210 3260,210 3300,210 3340,210 3380,210 3420,210 3460,210 3500,210 3540,210 3580,210 3620,210
  other v3: 3625,550 3665,550 3705,550 3625,590 3665,590 3705,590 3625,630 3665,630 3705,630 3625,670 3665,670 3705,670
RES: C12.1 U1.14 | length 133.9
  Bottom Layer w10: U1.14@2430.24,1395.94 2510.39,1395.94 2534,1419.56 2539.56,1419.56 C12.1@2550,1430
